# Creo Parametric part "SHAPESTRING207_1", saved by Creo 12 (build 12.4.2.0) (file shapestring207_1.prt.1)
Units: Custom; MM, KILOGRAM, SECS

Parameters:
  PTC_WM_ITERATION = "0"
  PTC_WM_VERSION = "-.0"
  PTC_WM_LIFECYCLE_STATE = "In Work"
  PTC_WM_LIFECYCLE = "MO_CADDocument"
  PTC_WM_CREATED_BY = "Maximilian Roepper (Z0017RMS: MO)"
  PTC_WM_CREATED_ON = "18-Sep-26 11:36:42 AM"
  PTC_WM_MODIFIED_BY = "Maximilian Roepper (Z0017RMS: MO)"
  PTC_WM_MODIFIED_ON = "18-Sep-26 11:36:46 AM"
  PDMLINKNUMBER = "PDM000071455124"
  PTC_WM_NAME = "shapestring207_1.prt"
  PTC_WM_NUMBER = "PDM000071455124"

Other parameters: WEIGHT, WEIGHT_FACTOR, WEIGHT_ADD, _MASS_TEMP, _DIFF_TEMP, MC_ERRORS, SUPPLIER

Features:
  1. coordinate system
  2. datum plane "PRT_YZ"
  3. datum plane "PRT_XY"
  4. datum plane "PRT_XZ"
  5. coordinate system
  6. datum axis
  7. datum axis
  8. datum axis
  9. coordinate system
  10. imported feature

Other named items: PRT, SIEMENS_MO, DRW_VIEW_ORG, PRT_X, PRT_Y, PRT_Z, CS0, ROUGH_GROB

Layers: 00_STD_CSYS-KSYS, 01_STD_PLANES-EBENEN, 02_STD_AXES-ACHSEN, 03_STD_CSYS-KSYS, 24_IMPORT_FEAT-IMPORT_KE, INTFCLR

Surfaces: 1 plane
